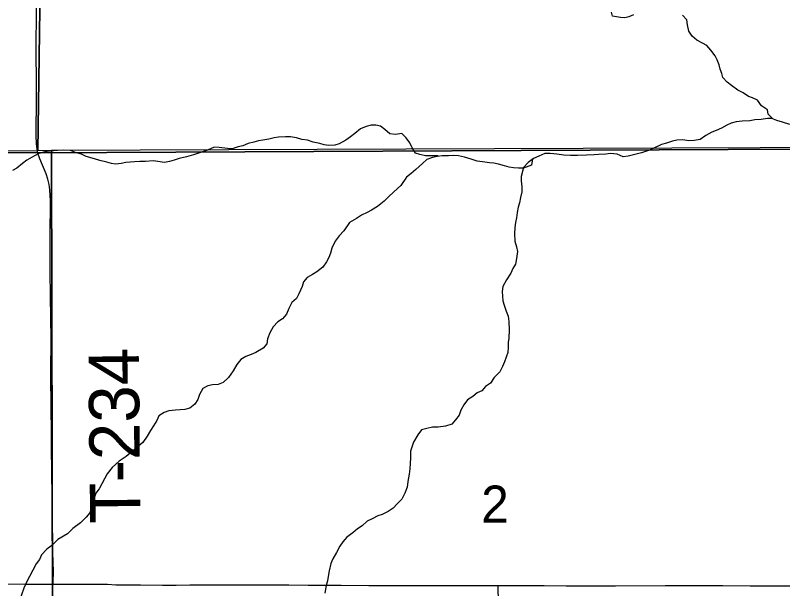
# Model space of a CAD drawing. Extents: x 0 to 34, y 0 to 22.
# Drawn here: x 7.469 to 8.336, y 17.922 to 18.57 of the extents above; entities that cross this region are included whole.
import ezdxf

# ---------------------------------------------------------------- set-up
doc = ezdxf.new("R2010")
doc.units = 0
for name, color, linetype in [('Default', 7, 'Continuous'), ('GM_X_County_Road', 7, 'Continuous'), ('GM_X_Minor_River', 7, 'Continuous'), ('GM_X_Section', 7, 'Continuous'), ('GM_X_Section_Text', 7, 'Continuous'), ('GM_X_Township_Road', 7, 'Continuous'), ('GM_X_Township_Road_Text', 7, 'Continuous')]:
    doc.layers.add(name, color=color, linetype=linetype)

msp = doc.modelspace()

# ---------------------------------------------------------------- linework, layer by layer
at = {"layer": 'Default'}
for points in [[(6.47549, 18.41735), (6.68269, 18.41817), (7.49471, 18.41489), (8.50798, 18.41991), (8.78884, 18.42547), (8.82115, 18.42594), (8.9, 18.4271), (8.9, 20.89996), (2.60322, 20.89996)], [(8.9, 14.36959), (8.9, 18.4271), (8.82115, 18.42594), (8.78884, 18.42547), (8.50798, 18.41991), (7.49471, 18.41489), (6.68269, 18.41817), (6.47549, 18.41735)]]:
    msp.add_lwpolyline(points, dxfattribs=at)
at = {"layer": 'GM_X_County_Road'}
for points in [[(7.45261, 17.92782), (7.48054, 17.92736), (7.48981, 17.92752), (7.50132, 17.92738), (7.51217, 17.9275)], [(7.51217, 17.9275), (7.51326, 17.92751), (7.5333, 17.92773), (7.53973, 17.92766), (7.55138, 17.92765), (7.56418, 17.92751), (7.57344, 17.92743), (7.58274, 17.92697), (7.59352, 17.92693), (7.61064, 17.92666), (7.63544, 17.92658), (7.65097, 17.9266), (7.6665, 17.92668), (7.69755, 17.92671), (7.74105, 17.92663), (7.77833, 17.92663), (7.80005, 17.92651), (7.81868, 17.92636), (7.83732, 17.92623), (7.8684, 17.92609), (7.90257, 17.92609), (7.92739, 17.92607), (7.96464, 17.92589), (7.98016, 17.92594), (8.00124, 17.92594), (8.0145, 17.92595)], [(8.0145, 17.92595), (8.04464, 17.92617), (8.06638, 17.926), (8.09124, 17.92579), (8.11551, 17.92582), (8.14715, 17.92582), (8.20306, 17.92605), (8.23412, 17.92594), (8.2683, 17.9259), (8.2989, 17.92564), (8.31804, 17.92549), (8.33041, 17.92569), (8.34565, 17.92564)], [(8.01668, 17.53489), (8.01663, 17.53964), (8.01637, 17.57381), (8.01612, 17.60796), (8.01555, 17.64835), (8.01555, 17.67006), (8.0153, 17.72274), (8.01523, 17.74758), (8.01535, 17.78795), (8.01501, 17.83143), (8.01481, 17.88112), (8.01481, 17.90598), (8.0145, 17.92595)]]:
    msp.add_lwpolyline(points, dxfattribs=at)
at = {"layer": 'GM_X_Minor_River'}
for points in [[(8.16722, 18.57085), (8.16226, 18.56857), (8.15769, 18.56743), (8.15272, 18.56781), (8.14356, 18.56934), (8.14241, 18.5739)], [(8.3245, 18.45327), (8.31937, 18.45859), (8.3186, 18.46353), (8.31172, 18.4681), (8.3075, 18.47418), (8.30177, 18.47685), (8.29719, 18.47837), (8.29108, 18.48256), (8.28496, 18.4856), (8.27808, 18.49093), (8.27311, 18.49473), (8.26814, 18.50006), (8.26698, 18.50462), (8.26506, 18.50919), (8.2639, 18.51413), (8.26198, 18.51984), (8.25968, 18.5244), (8.2547, 18.53087), (8.25011, 18.5362), (8.24515, 18.53886), (8.23903, 18.54229), (8.23368, 18.54647), (8.22985, 18.55218), (8.22831, 18.55941), (8.22753, 18.56511), (8.22255, 18.57044)], [(8.34382, 18.44678), (8.33542, 18.44945), (8.32931, 18.45135), (8.32358, 18.45364), (8.31862, 18.45364), (8.31137, 18.4525), (8.3045, 18.45213), (8.29878, 18.45099), (8.29001, 18.45062), (8.28314, 18.44986), (8.2778, 18.44834), (8.27284, 18.44606), (8.26675, 18.44264), (8.26065, 18.43998), (8.25569, 18.43809), (8.24883, 18.43429), (8.24273, 18.42973), (8.23587, 18.42859), (8.22976, 18.42821), (8.22289, 18.42936), (8.2164, 18.42898), (8.21144, 18.42784), (8.20458, 18.42557), (8.19886, 18.42443), (8.19047, 18.42025), (8.18437, 18.41759), (8.17637, 18.41494), (8.16149, 18.41114), (8.15577, 18.41038), (8.14889, 18.41343), (8.14126, 18.41419), (8.13592, 18.41344), (8.1279, 18.41306), (8.12294, 18.41268), (8.11417, 18.41231), (8.10425, 18.41193), (8.09623, 18.41194), (8.0886, 18.41232), (8.08096, 18.41347), (8.07333, 18.41423), (8.06722, 18.41423), (8.06036, 18.4112), (8.05426, 18.40854), (8.04855, 18.40398), (8.04322, 18.39828), (8.04057, 18.38801), (8.04058, 18.38307), (8.04136, 18.3766), (8.04137, 18.3709), (8.03986, 18.36444), (8.03873, 18.35835), (8.03722, 18.35341), (8.03609, 18.34733), (8.03534, 18.34124), (8.03421, 18.3363), (8.03345, 18.33059), (8.03309, 18.32337), (8.03349, 18.315), (8.03542, 18.30854), (8.03619, 18.30321), (8.03506, 18.29561), (8.03394, 18.28915)], [(7.94666, 18.41096), (7.94664, 18.41126), (7.93251, 18.41127), (7.92602, 18.41279), (7.92106, 18.41432), (7.91761, 18.4204), (7.91493, 18.42611), (7.91071, 18.43181), (7.90574, 18.43676), (7.89849, 18.43562), (7.89238, 18.43638), (7.88665, 18.44133), (7.88168, 18.44514), (7.87633, 18.44628), (7.87099, 18.44628), (7.86565, 18.44477), (7.85917, 18.44211), (7.85269, 18.43679), (7.84774, 18.43299), (7.84241, 18.42919), (7.83517, 18.42501), (7.83021, 18.42349), (7.82334, 18.42311), (7.818, 18.42388), (7.81303, 18.4254), (7.80578, 18.42693), (7.79928, 18.42921), (7.7928, 18.42998), (7.78669, 18.43188), (7.78019, 18.43303), (7.77447, 18.43303), (7.76646, 18.43265), (7.7615, 18.4319), (7.75578, 18.43038), (7.74891, 18.42924), (7.74395, 18.42848), (7.73861, 18.42696), (7.73213, 18.42545), (7.72641, 18.42279), (7.72107, 18.42165), (7.7142, 18.41937), (7.70886, 18.41976), (7.6997, 18.4209), (7.69397, 18.42128), (7.68635, 18.41787), (7.67834, 18.41521), (7.67071, 18.41255), (7.66271, 18.41028), (7.65431, 18.40838), (7.64859, 18.40648), (7.64364, 18.40496), (7.63792, 18.40383), (7.63028, 18.40497), (7.62494, 18.40573), (7.61654, 18.40498), (7.61005, 18.40498), (7.60395, 18.4046), (7.59899, 18.40423), (7.59403, 18.40385), (7.58907, 18.40271), (7.58297, 18.40195), (7.578, 18.40272), (7.57265, 18.40424), (7.56464, 18.40615), (7.55891, 18.40805), (7.54936, 18.41072), (7.54401, 18.41338), (7.53752, 18.41529), (7.53179, 18.41757), (7.52377, 18.41796), (7.51691, 18.41758), (7.50813, 18.41683), (7.50279, 18.41607), (7.49592, 18.41417), (7.48754, 18.40961), (7.48258, 18.40657), (7.47763, 18.40277), (7.47116, 18.39745), (7.4662, 18.3948)], [(8.05343, 18.40787), (8.05237, 18.40093), (8.04322, 18.39752), (8.0375, 18.39752), (8.03177, 18.3979), (8.02681, 18.39866), (8.02184, 18.40019), (8.01497, 18.40209), (8.00962, 18.40324), (8.00466, 18.40362), (7.99702, 18.40477), (7.99092, 18.40553), (7.98404, 18.40781), (7.9764, 18.4101), (7.96991, 18.41163), (7.96419, 18.41201), (7.95846, 18.41163), (7.95121, 18.41126), (7.94549, 18.41088), (7.94053, 18.40974), (7.93405, 18.40746), (7.9291, 18.4029), (7.92148, 18.39606), (7.91615, 18.3915), (7.9112, 18.38732), (7.90473, 18.37782), (7.89674, 18.3706), (7.89064, 18.36528), (7.88569, 18.36034), (7.87846, 18.35426), (7.8716, 18.35008), (7.86665, 18.34742), (7.86016, 18.34438), (7.85445, 18.34058), (7.84683, 18.33602), (7.84036, 18.3269), (7.83503, 18.3212), (7.83047, 18.31512), (7.82667, 18.30713), (7.82516, 18.30143), (7.82326, 18.29649), (7.8206, 18.29155), (7.81642, 18.28585), (7.80994, 18.28052), (7.80499, 18.27748), (7.79889, 18.27407), (7.7947, 18.26912), (7.79319, 18.2638), (7.78939, 18.25544), (7.78673, 18.25012), (7.78178, 18.24594), (7.77836, 18.23909), (7.77571, 18.23263), (7.77114, 18.22731), (7.7658, 18.22389), (7.76048, 18.21819), (7.75668, 18.21135), (7.75402, 18.20488), (7.75327, 18.19918), (7.74908, 18.19424), (7.74108, 18.1893), (7.73575, 18.18702), (7.72965, 18.18474), (7.72393, 18.18132), (7.71936, 18.17562), (7.71518, 18.1684), (7.71024, 18.16118), (7.70414, 18.15548), (7.69843, 18.1532), (7.69194, 18.15282), (7.6866, 18.15169), (7.68126, 18.14865), (7.67746, 18.1418), (7.67557, 18.1361), (7.67215, 18.13078), (7.66643, 18.12622), (7.66071, 18.1247), (7.65537, 18.12432), (7.65041, 18.12395), (7.64278, 18.12319), (7.63744, 18.12167), (7.63134, 18.11787), (7.62906, 18.11255), (7.62526, 18.10647), (7.62184, 18.10115), (7.61842, 18.09469), (7.61348, 18.08746), (7.60624, 18.08138), (7.60129, 18.07758), (7.59443, 18.07188), (7.58681, 18.06656), (7.57882, 18.05934), (7.57311, 18.05212), (7.56703, 18.04072), (7.56399, 18.03539), (7.56019, 18.03045), (7.55829, 18.02475), (7.55678, 18.01829), (7.55526, 18.01334), (7.55337, 18.00802), (7.54956, 18.00308)], [(8.03394, 18.28915), (8.03128, 18.2842), (8.029, 18.27888), (8.02406, 18.27128), (8.01988, 18.26368), (8.01912, 18.25835), (8.01991, 18.24771), (8.02145, 18.24276), (8.02376, 18.23591), (8.02568, 18.23021), (8.02646, 18.22413), (8.02686, 18.215), (8.0265, 18.20549), (8.02575, 18.20055), (8.02576, 18.19523), (8.0254, 18.18914), (8.0216, 18.17888), (8.01933, 18.17355), (8.01629, 18.16747), (8.0102, 18.16101), (8.00601, 18.15455), (8.0003, 18.15075), (7.99611, 18.14581), (7.99078, 18.14353), (7.98582, 18.13973), (7.98011, 18.13593), (7.97592, 18.13023), (7.9725, 18.12415), (7.97061, 18.11845), (7.96642, 18.11312), (7.96224, 18.10818), (7.95499, 18.10591), (7.94698, 18.10477), (7.94049, 18.10477), (7.93401, 18.10325), (7.92791, 18.10174), (7.92372, 18.09642), (7.91878, 18.08805), (7.91575, 18.07779), (7.91539, 18.07018), (7.91502, 18.06372), (7.91465, 18.05802), (7.9139, 18.05193), (7.9124, 18.04357), (7.91165, 18.0371), (7.90899, 18.03026), (7.90596, 18.02342), (7.90063, 18.01848), (7.89606, 18.01353), (7.89034, 18.00973), (7.88348, 18.00632), (7.87852, 18.0048), (7.87243, 18.00138), (7.86671, 17.99872), (7.861, 17.9934), (7.85566, 17.98998), (7.85033, 17.98542), (7.84385, 17.98048), (7.83929, 17.97554), (7.83586, 17.9706), (7.83206, 17.96338), (7.82788, 17.95615), (7.82561, 17.95083), (7.82372, 17.94247), (7.82258, 17.93638), (7.82183, 17.93144), (7.82032, 17.92612), (7.81881, 17.91737)], [(7.54956, 18.00308), (7.54309, 17.997), (7.53433, 17.99054), (7.52824, 17.98446), (7.51757, 17.978), (7.51071, 17.97116), (7.505, 17.96698), (7.49891, 17.96052), (7.49663, 17.95558), (7.49283, 17.95064), (7.48523, 17.93619), (7.48219, 17.92973), (7.47915, 17.92289), (7.4765, 17.91566), (7.47347, 17.90654), (7.47119, 17.89931), (7.4693, 17.89399)]]:
    msp.add_lwpolyline(points, dxfattribs=at)
at = {"layer": 'GM_X_Section'}
for points in [[(6.48237, 19.42911), (7.50907, 19.42955), (7.49466, 18.41721), (6.47934, 18.41607)], [(7.50907, 19.42955), (8.52175, 19.42955), (8.51073, 18.42139), (7.5102, 18.41729), (7.49466, 18.41721)], [(8.51735, 17.53489), (8.51073, 18.42139), (7.5102, 18.41729), (7.51214, 17.53489)], [(7.51214, 17.53489), (7.5102, 18.41729), (7.49466, 18.41721), (6.47934, 18.41607), (6.49307, 17.53489)]]:
    msp.add_lwpolyline(points, close=True, dxfattribs=at)
at = {"layer": 'GM_X_Township_Road'}
for points in [[(7.49492, 18.41435), (7.49398, 18.41887), (7.49318, 18.42502), (7.49278, 18.43431), (7.4931, 18.45289), (7.49324, 18.45909), (7.49323, 18.46838), (7.49326, 18.48389), (7.49304, 18.53979), (7.49332, 18.56774), (7.49444, 18.63296), (7.49528, 18.68577), (7.49571, 18.72305), (7.49629, 18.76344), (7.49676, 18.7945), (7.49755, 18.8411), (7.49837, 18.87835), (7.49921, 18.91559), (7.49986, 18.9404), (7.50034, 18.95592), (7.50126, 18.98387), (7.50144, 19.00561), (7.50145, 19.02081)], [(7.51217, 17.9275), (7.51219, 17.92945), (7.51234, 17.94255), (7.51222, 17.95176), (7.51191, 17.96412), (7.51157, 17.97961), (7.51145, 17.99201), (7.51121, 18.00749), (7.51099, 18.02605), (7.51055, 18.05394), (7.51019, 18.08181), (7.51012, 18.10041), (7.51004, 18.12521), (7.50961, 18.16549), (7.50983, 18.20578), (7.5096, 18.22744), (7.50891, 18.28003), (7.50872, 18.3141), (7.50885, 18.33268), (7.50924, 18.34821), (7.5091, 18.36055), (7.50829, 18.37292), (7.5075, 18.37906), (7.50608, 18.38508), (7.50408, 18.39093), (7.49693, 18.40819), (7.49492, 18.41435)]]:
    msp.add_lwpolyline(points, dxfattribs=at)

# ---------------------------------------------------------------- texts
at = {"layer": 'GM_X_Section_Text'}
msp.add_text('2', height=0.04186, rotation=0.00001, dxfattribs=at).set_placement((7.99539, 17.99707))
at = {"layer": 'GM_X_Township_Road_Text'}
msp.add_text('T-234', height=0.056818, rotation=90.55731, dxfattribs=at).set_placement((7.61067, 17.99625))

doc.saveas('drawing.dxf')
